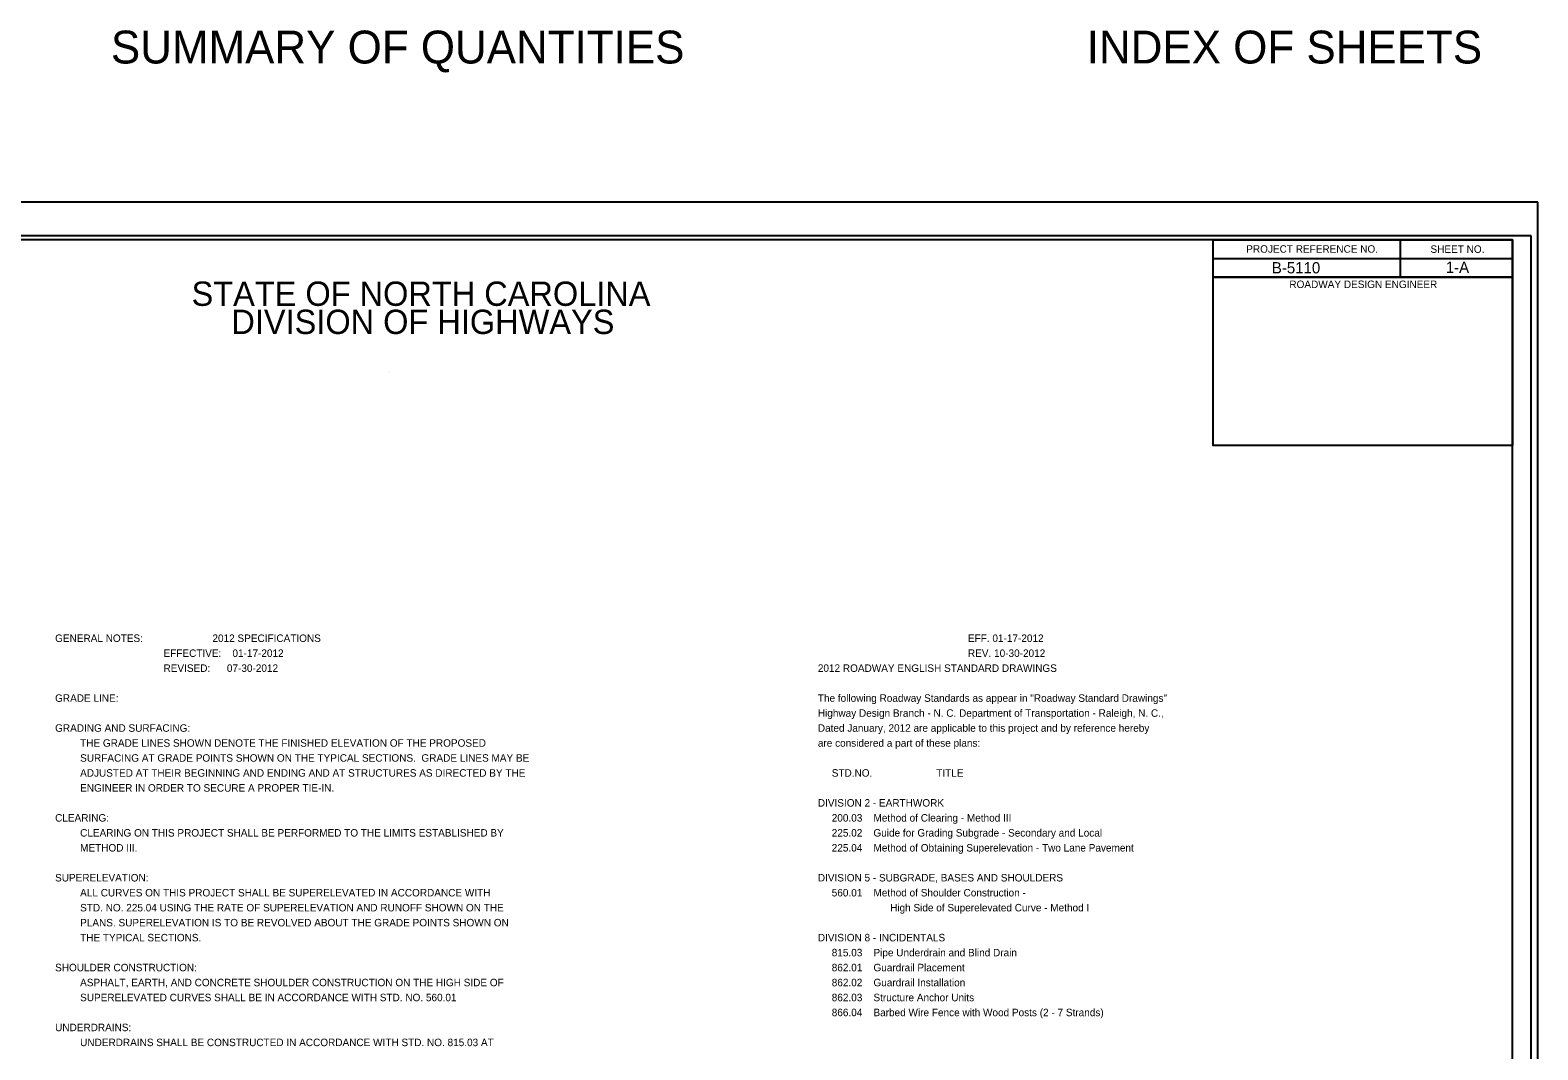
# Model space of a CAD drawing. Extents: x 1728265 to 1732106, y 539919 to 543766.
# Drawn here: x 1730130 to 1731137, y 543084 to 543766 of the extents above; entities that cross this region are included whole.
import ezdxf

# ---------------------------------------------------------------- set-up
doc = ezdxf.new("R2010")
doc.units = 0
for name, color, linetype in [('Default', 7, 'Continuous'), ('Sheet Border Standard 30in CELL', 7, 'Continuous'), ('Sheet Cutting Line CELL', 7, 'Continuous'), ('Sheet Data Field CELL', 7, 'Continuous'), ('Sheet Plot Border Inside CELL', 7, 'Continuous'), ('Sheet Plot Border Outside CELL', 7, 'Continuous'), ('Sheet Summary CELL', 7, 'Continuous')]:
    doc.layers.add(name, color=color, linetype=linetype)

msp = doc.modelspace()

# ---------------------------------------------------------------- linework, layer by layer
at = {"layer": 'Sheet Border Standard 30in CELL'}
msp.add_lwpolyline([(1730920.3, 543600.6), (1731120.3, 543600.6), (1731120.3, 543488.1), (1730920.3, 543488.1)], close=True, dxfattribs=at)
at = {"layer": 'Sheet Cutting Line CELL'}
msp.add_line((1731137.3, 543650.6), (1729453.3, 543650.6), dxfattribs=at)
at = {"layer": 'Sheet Plot Border Inside CELL'}
msp.add_lwpolyline([(1731132.8, 543628.2), (1729466.3, 543628.2), (1729466.3, 542573.1), (1731132.8, 542573.1)], close=True, dxfattribs=at)
at = {"layer": 'Sheet Plot Border Outside CELL'}
msp.add_lwpolyline([(1731137.3, 543650.6), (1729453.3, 543650.6), (1729453.3, 542550.6), (1731137.3, 542550.6)], close=True, dxfattribs=at)
at = {"layer": 'Sheet Summary CELL'}
for p, q in [((1731045.3, 543625.6), (1731045.3, 543600.6)), ((1730920.3, 543613.1), (1731120.3, 543613.1)), ((1730920.3, 543600.6), (1731120.3, 543600.6)), ((1730369.9, 543536.8), (1730369.9, 543536.8))]:
    msp.add_line(p, q, dxfattribs=at)
for points in [[(1731120.3, 543625.6), (1729620.3, 543625.6), (1729620.3, 542575.6), (1731120.3, 542575.6)], [(1730920.3, 543625.6), (1731120.3, 543625.6), (1731120.3, 543600.6), (1730920.3, 543600.6)]]:
    msp.add_lwpolyline(points, close=True, dxfattribs=at)

# ---------------------------------------------------------------- texts
at = {"layer": 'Default'}
for s, p in [('GENERAL NOTES:                         2012 SPECIFICATIONS', (1730146.5, 543356.9)), ('                                                      EFF. 01-17-2012', (1730656.2, 543356.9)), ('                                       EFFECTIVE:    01-17-2012', (1730146.5, 543346.9)), ('                                                      REV. 10-30-2012', (1730656.2, 543346.9)), ('                                       REVISED:      07-30-2012', (1730146.5, 543336.9)), ('2012 ROADWAY ENGLISH STANDARD DRAWINGS', (1730656.2, 543336.9)), ('GRADE LINE:  ', (1730146.5, 543316.9)), ('The following Roadway Standards as appear in "Roadway Standard Drawings"', (1730656.2, 543316.9)), ('Highway Design Branch - N. C. Department of Transportation - Raleigh, N. C.,', (1730656.2, 543306.9)), ('GRADING AND SURFACING:  ', (1730146.5, 543296.9)), ('Dated January, 2012 are applicable to this project and by reference hereby', (1730656.2, 543296.9)), ('         THE GRADE LINES SHOWN DENOTE THE FINISHED ELEVATION OF THE PROPOSED ', (1730146.5, 543286.9)), ('are considered a part of these plans:', (1730656.2, 543286.9)), ('         SURFACING AT GRADE POINTS SHOWN ON THE TYPICAL SECTIONS.  GRADE LINES MAY BE ', (1730146.5, 543276.9)), ('         ADJUSTED AT THEIR BEGINNING AND ENDING AND AT STRUCTURES AS DIRECTED BY THE ', (1730146.5, 543266.9)), ('     STD.NO.                       TITLE', (1730656.2, 543266.9)), ('         ENGINEER IN ORDER TO SECURE A PROPER TIE-IN.  ', (1730146.5, 543256.9)), ('DIVISION 2 - EARTHWORK', (1730656.2, 543246.9)), ('CLEARING:  ', (1730146.5, 543236.9)), ('     200.03    Method of Clearing - Method III', (1730656.2, 543236.9)), ('         CLEARING ON THIS PROJECT SHALL BE PERFORMED TO THE LIMITS ESTABLISHED BY ', (1730146.5, 543226.9)), ('     225.02    Guide for Grading Subgrade - Secondary and Local', (1730656.2, 543226.9)), ('         METHOD III.', (1730146.5, 543216.9)), ('     225.04    Method of Obtaining Superelevation - Two Lane Pavement', (1730656.2, 543216.9)), ('SUPERELEVATION:  ', (1730146.5, 543196.9)), ('DIVISION 5 - SUBGRADE, BASES AND SHOULDERS', (1730656.2, 543196.9)), ('         ALL CURVES ON THIS PROJECT SHALL BE SUPERELEVATED IN ACCORDANCE WITH', (1730146.5, 543186.9)), ('     560.01    Method of Shoulder Construction - ', (1730656.2, 543186.9)), ('         STD. NO. 225.04 USING THE RATE OF SUPERELEVATION AND RUNOFF SHOWN ON THE', (1730146.5, 543176.9)), ('                          High Side of Superelevated Curve - Method I', (1730656.2, 543176.9)), ('         PLANS. SUPERELEVATION IS TO BE REVOLVED ABOUT THE GRADE POINTS SHOWN ON', (1730146.5, 543166.9)), ('         THE TYPICAL SECTIONS.  ', (1730146.5, 543156.9)), ('DIVISION 8 - INCIDENTALS', (1730656.2, 543156.9)), ('     815.03    Pipe Underdrain and Blind Drain', (1730656.2, 543146.9)), ('SHOULDER CONSTRUCTION:  ', (1730146.5, 543136.9)), ('     862.01    Guardrail Placement', (1730656.2, 543136.9)), ('         ASPHALT, EARTH, AND CONCRETE SHOULDER CONSTRUCTION ON THE HIGH SIDE OF', (1730146.5, 543126.9)), ('     862.02    Guardrail Installation', (1730656.2, 543126.9)), ('         SUPERELEVATED CURVES SHALL BE IN ACCORDANCE WITH STD. NO. 560.01', (1730146.5, 543116.9)), ('     862.03    Structure Anchor Units', (1730656.2, 543116.9)), ('     866.04    Barbed Wire Fence with Wood Posts (2 - 7 Strands)', (1730656.2, 543106.9)), ('UNDERDRAINS:  ', (1730146.5, 543096.9)), ('         UNDERDRAINS SHALL BE CONSTRUCTED IN ACCORDANCE WITH STD. NO. 815.03 AT ', (1730146.5, 543086.9))]:
    msp.add_text(s, height=5, dxfattribs=at).set_placement(p)
at = {"layer": 'Sheet Border Standard 30in CELL'}
msp.add_text('ROADWAY DESIGN ENGINEER', height=5, dxfattribs=at).set_placement((1730971.3, 543593.3))
at = {"layer": 'Sheet Data Field CELL'}
for s, p in [(' B-5110  ', (1730956.8, 543603.1)), ('1-A', (1731075.8, 543603.4))]:
    msp.add_text(s, height=7.5, dxfattribs=at).set_placement(p)
at = {"layer": 'Sheet Summary CELL'}
for s, height, p in [('SUMMARY OF QUANTITIES', 21.95, (1730183.8, 543743.3)), ('INDEX OF SHEETS', 21.95, (1730835.9, 543743.3)), ('PROJECT REFERENCE NO.', 5, (1730942.5, 543616.9)), ('SHEET NO.', 5, (1731065.6, 543616.8)), ('STATE OF NORTH CAROLINA', 16.25, (1730237.7, 543581.4)), ('DIVISION OF HIGHWAYS', 16.25, (1730264.3, 543562.6))]:
    msp.add_text(s, height=height, dxfattribs=at).set_placement(p)

doc.saveas('drawing.dxf')
